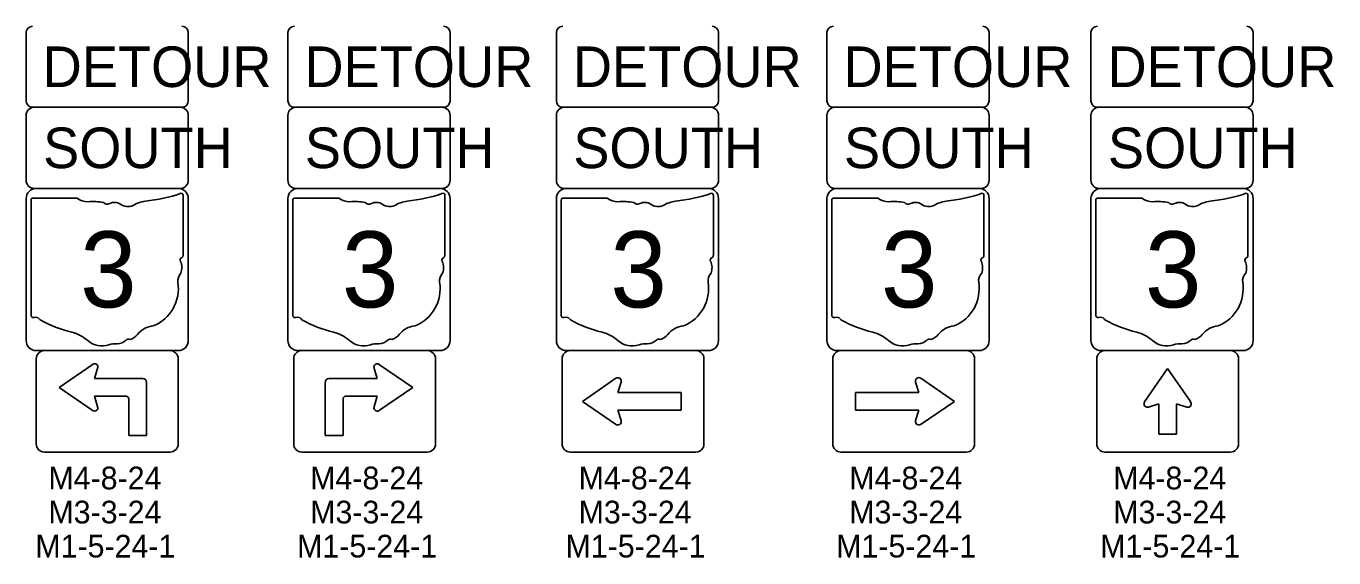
# Model space of a CAD drawing. Extents: x -15.3 to 34, y 0 to 22.
# Drawn here: x -14.79 to -6.73, y 8.37 to 11.65 of the extents above; entities that cross this region are included whole.
import ezdxf

# ---------------------------------------------------------------- set-up
doc = ezdxf.new("R2010")
doc.units = 0
doc.layers.add('SC_Scratch1', color=7, linetype='Continuous')
doc.layers.add('SN_P_Signs', color=7, linetype='Continuous')

msp = doc.modelspace()

# ---------------------------------------------------------------- linework, layer by layer
at = {"layer": 'SN_P_Signs'}
for p, q in [((-14.7405, 11.15), (-13.8405, 11.15)), ((-13.1262, 11.15), (-12.2262, 11.15)), ((-11.4709, 11.15), (-10.5709, 11.15)), ((-9.8019, 11.15), (-8.9019, 11.15)), ((-8.1739, 11.15), (-7.2739, 11.15)), ((-14.7905, 10.7), (-14.7905, 11.1)), ((-13.7905, 11.1), (-13.7905, 10.7)), ((-13.1762, 10.7), (-13.1762, 11.1)), ((-12.1762, 11.1), (-12.1762, 10.7)), ((-11.5209, 10.7), (-11.5209, 11.1)), ((-10.5209, 11.1), (-10.5209, 10.7)), ((-9.8519, 10.7), (-9.8519, 11.1)), ((-8.8519, 11.1), (-8.8519, 10.7)), ((-8.2239, 10.7), (-8.2239, 11.1)), ((-7.2239, 11.1), (-7.2239, 10.7)), ((-13.8405, 10.65), (-14.7405, 10.65)), ((-12.2262, 10.65), (-13.1262, 10.65)), ((-10.5709, 10.65), (-11.4709, 10.65)), ((-8.9019, 10.65), (-9.8019, 10.65)), ((-7.2739, 10.65), (-8.1739, 10.65)), ((-14.7599, 10.578), (-14.7599, 9.8664)), ((-14.4761, 10.5902), (-14.7507, 10.5902)), ((-13.8224, 10.2356), (-13.8224, 10.6078)), ((-13.1456, 10.578), (-13.1456, 9.8664)), ((-12.8619, 10.5902), (-13.1364, 10.5902)), ((-12.2082, 10.2356), (-12.2082, 10.6078)), ((-11.4903, 10.578), (-11.4903, 9.8664)), ((-11.2065, 10.5902), (-11.4811, 10.5902)), ((-10.5528, 10.2356), (-10.5528, 10.6078)), ((-9.8213, 10.578), (-9.8213, 9.8664)), ((-9.5376, 10.5902), (-9.8121, 10.5902)), ((-8.8838, 10.2356), (-8.8838, 10.6078)), ((-8.1934, 10.578), (-8.1934, 9.8664)), ((-7.9096, 10.5902), (-8.1841, 10.5902)), ((-7.2559, 10.2356), (-7.2559, 10.6078)), ((-13.8225, 10.2357), (-13.8224, 10.2356)), ((-12.2083, 10.2357), (-12.2082, 10.2356)), ((-10.5529, 10.2357), (-10.5528, 10.2356)), ((-8.8839, 10.2357), (-8.8838, 10.2356)), ((-7.256, 10.2357), (-7.2559, 10.2356)), ((-14.728, 9.075), (-14.728, 9.6)), ((-14.678, 9.65), (-13.903, 9.65)), ((-13.853, 9.6), (-13.853, 9.075)), ((-13.1408, 9.6), (-13.1408, 9.075)), ((-12.3158, 9.65), (-13.0908, 9.65)), ((-12.2658, 9.075), (-12.2658, 9.6)), ((-11.4855, 9.6), (-11.4855, 9.075)), ((-10.6605, 9.65), (-11.4355, 9.65)), ((-10.6605, 9.65), (-10.6605, 9.65)), ((-10.6105, 9.075), (-10.6105, 9.6)), ((-9.8165, 9.075), (-9.8165, 9.6)), ((-9.7665, 9.65), (-8.9915, 9.65)), ((-8.9415, 9.6), (-8.9415, 9.075)), ((-8.1886, 9.075), (-8.1886, 9.6)), ((-8.1386, 9.65), (-7.3636, 9.65)), ((-7.3136, 9.6), (-7.3136, 9.075)), ((-14.3833, 9.5632), (-14.5873, 9.4234)), ((-14.3685, 9.4781), (-14.3477, 9.5484)), ((-12.6253, 9.4781), (-12.6461, 9.5484)), ((-12.6105, 9.5632), (-12.4065, 9.4234)), ((-7.8932, 9.3337), (-7.7511, 9.5406)), ((-7.7511, 9.5406), (-7.6113, 9.3366)), ((-14.0716, 9.4781), (-14.3685, 9.4781)), ((-14.0716, 9.4781), (-14.0716, 9.4781)), ((-14.0482, 9.1265), (-14.0482, 9.4547)), ((-12.9456, 9.1265), (-12.9456, 9.4547)), ((-12.9222, 9.4781), (-12.6253, 9.4781)), ((-12.9222, 9.4781), (-12.9222, 9.4781)), ((-11.3605, 9.3375), (-11.1536, 9.4797)), ((-11.1219, 9.4564), (-11.1418, 9.3922)), ((-9.3052, 9.4564), (-9.2853, 9.3922)), ((-9.0665, 9.3375), (-9.2735, 9.4797)), ((-14.5873, 9.4234), (-14.3833, 9.2837)), ((-14.3477, 9.2984), (-14.3685, 9.3687)), ((-14.3685, 9.3687), (-14.1732, 9.3687)), ((-12.6253, 9.3687), (-12.8206, 9.3687)), ((-12.6461, 9.2984), (-12.6253, 9.3687)), ((-12.4065, 9.4234), (-12.6105, 9.2837)), ((-11.1418, 9.3922), (-10.7512, 9.3922)), ((-10.7512, 9.3922), (-10.7512, 9.2828)), ((-9.2853, 9.3922), (-9.6759, 9.3922)), ((-9.6759, 9.3922), (-9.6759, 9.2828)), ((-14.1576, 9.3531), (-14.1576, 9.1265)), ((-12.8362, 9.3531), (-12.8362, 9.1265)), ((-11.1565, 9.1978), (-11.3605, 9.3375)), ((-10.7512, 9.2828), (-11.1418, 9.2828)), ((-11.1418, 9.2828), (-11.1219, 9.2187)), ((-9.6759, 9.2828), (-9.2853, 9.2828)), ((-9.2853, 9.2828), (-9.3052, 9.2187)), ((-9.2705, 9.1978), (-9.0665, 9.3375)), ((-7.8058, 9.3219), (-7.8699, 9.3019)), ((-7.8058, 9.1344), (-7.8058, 9.3219)), ((-7.6322, 9.3019), (-7.6964, 9.3219)), ((-7.6964, 9.3219), (-7.6964, 9.1344)), ((-14.1576, 9.1265), (-14.0482, 9.1265)), ((-14.1576, 9.1265), (-14.0482, 9.1265)), ((-12.8362, 9.1265), (-12.9456, 9.1265)), ((-7.6964, 9.1344), (-7.8058, 9.1344)), ((-13.903, 9.025), (-14.678, 9.025)), ((-13.0908, 9.025), (-12.3158, 9.025)), ((-11.4355, 9.025), (-10.6605, 9.025)), ((-8.9915, 9.025), (-9.7665, 9.025)), ((-7.3636, 9.025), (-8.1386, 9.025))]:
    msp.add_line(p, q, dxfattribs=at)
for points in [[(-14.7905, 11.61), (-14.7905, 11.19)], [(-13.7905, 11.19), (-13.7905, 11.61)], [(-13.1762, 11.61), (-13.1762, 11.19)], [(-12.1762, 11.19), (-12.1762, 11.61)], [(-11.5209, 11.61), (-11.5209, 11.19)], [(-10.5209, 11.19), (-10.5209, 11.61)], [(-9.8519, 11.61), (-9.8519, 11.19)], [(-8.8519, 11.19), (-8.8519, 11.61)], [(-8.2239, 11.61), (-8.2239, 11.19)], [(-7.2239, 11.19), (-7.2239, 11.61)], [(-14.7505, 11.15), (-13.8305, 11.15)], [(-13.1362, 11.15), (-12.2162, 11.15)], [(-11.4809, 11.15), (-10.5609, 11.15)], [(-9.8119, 11.15), (-8.8919, 11.15)], [(-8.1839, 11.15), (-7.2639, 11.15)], [(-13.853, 10.65), (-14.728, 10.65)], [(-12.2387, 10.65), (-13.1137, 10.65)], [(-10.5834, 10.65), (-11.4584, 10.65)], [(-8.9144, 10.65), (-9.7894, 10.65)], [(-7.2864, 10.65), (-8.1614, 10.65)], [(-14.7905, 10.5875), (-14.7905, 9.7125)], [(-13.7905, 9.7125), (-13.7905, 10.5875)], [(-13.1762, 10.5875), (-13.1762, 9.7125)], [(-12.1762, 9.7125), (-12.1762, 10.5875)], [(-11.5209, 10.5875), (-11.5209, 9.7125)], [(-10.5209, 9.7125), (-10.5209, 10.5875)], [(-9.8519, 10.5875), (-9.8519, 9.7125)], [(-8.8519, 9.7125), (-8.8519, 10.5875)], [(-8.2239, 10.5875), (-8.2239, 9.7125)], [(-7.2239, 9.7125), (-7.2239, 10.5875)], [(-14.728, 9.65), (-13.853, 9.65)], [(-13.1137, 9.65), (-12.2387, 9.65)], [(-11.4584, 9.65), (-10.5834, 9.65)], [(-9.7894, 9.65), (-8.9144, 9.65)], [(-8.1614, 9.65), (-7.2864, 9.65)]]:
    msp.add_lwpolyline(points, dxfattribs=at)
for centre, radius, start, end in [((-14.7505, 11.61), 0.04, 90, 180), ((-13.8305, 11.61), 0.04, 0, 90), ((-13.1362, 11.61), 0.04, 90, 180), ((-12.2162, 11.61), 0.04, 0, 90), ((-11.4809, 11.61), 0.04, 90, 180), ((-10.5609, 11.61), 0.04, 0, 90), ((-9.8119, 11.61), 0.04, 90, 180), ((-8.8919, 11.61), 0.04, 0, 90), ((-8.1839, 11.61), 0.04, 90, 180), ((-7.2639, 11.61), 0.04, 0, 90), ((-14.7505, 11.19), 0.04, 180, 270), ((-14.7405, 11.1), 0.05, 90, 180), ((-13.8405, 11.1), 0.05, 0, 90), ((-13.8305, 11.19), 0.04, 270, 0), ((-13.1362, 11.19), 0.04, 180, 270), ((-13.1262, 11.1), 0.05, 90, 180), ((-12.2262, 11.1), 0.05, 0, 90), ((-12.2162, 11.19), 0.04, 270, 0), ((-11.4809, 11.19), 0.04, 180, 270), ((-11.4709, 11.1), 0.05, 90, 180), ((-10.5709, 11.1), 0.05, 0, 90), ((-10.5609, 11.19), 0.04, 270, 0), ((-9.8119, 11.19), 0.04, 180, 270), ((-9.8019, 11.1), 0.05, 90, 180), ((-8.9019, 11.1), 0.05, 0, 90), ((-8.8919, 11.19), 0.04, 270, 0), ((-8.1839, 11.19), 0.04, 180, 270), ((-8.1739, 11.1), 0.05, 90, 180), ((-7.2739, 11.1), 0.05, 0, 90), ((-7.2639, 11.19), 0.04, 270, 0), ((-14.7405, 10.7), 0.05, 180, 270), ((-14.728, 10.5875), 0.0625, 90, 180), ((-13.853, 10.5875), 0.0625, 0, 90), ((-13.8405, 10.7), 0.05, 270, 0), ((-13.1262, 10.7), 0.05, 180, 270), ((-13.1137, 10.5875), 0.0625, 90, 180), ((-12.2387, 10.5875), 0.0625, 0, 90), ((-12.2262, 10.7), 0.05, 270, 0), ((-11.4709, 10.7), 0.05, 180, 270), ((-11.4584, 10.5875), 0.0625, 90, 180), ((-10.5834, 10.5875), 0.0625, 0, 90), ((-10.5709, 10.7), 0.05, 270, 0), ((-9.8019, 10.7), 0.05, 180, 270), ((-9.7894, 10.5875), 0.0625, 90, 180), ((-8.9144, 10.5875), 0.0625, 0, 90), ((-8.9019, 10.7), 0.05, 270, 0), ((-8.1739, 10.7), 0.05, 180, 270), ((-8.1614, 10.5875), 0.0625, 90, 180), ((-7.2864, 10.5875), 0.0625, 0, 90), ((-7.2739, 10.7), 0.05, 270, 0), ((-14.7492, 10.5795), 0.0109, 98.1301, 188.1301), ((-14.4108, 10.6728), 0.1053, 231.61951, 271.11188), ((-14.3758, 10.1907), 0.3782, 80.48669, 94.98827), ((-14.2454, 10.5009), 0.0632, 54.46668, 119.14113), ((-14.0296, 10.3729), 0.2, 97.34618, 120.76885), ((-14.1564, 11.5603), 0.9942, 275.84447, 288.90645), ((-13.8328, 10.6094), 0.0104, 351.86209, 97.738), ((-13.1349, 10.5795), 0.0109, 98.1301, 188.1301), ((-12.7965, 10.6728), 0.1053, 231.61951, 271.11188), ((-12.7616, 10.1907), 0.3782, 80.48669, 94.98827), ((-12.6311, 10.5009), 0.0632, 54.46668, 119.14113), ((-12.4153, 10.3729), 0.2, 97.34618, 120.76885), ((-12.5421, 11.5603), 0.9942, 275.84447, 288.90645), ((-12.2186, 10.6094), 0.0104, 351.86209, 97.738), ((-11.4796, 10.5795), 0.0109, 98.1301, 188.1301), ((-11.1412, 10.6728), 0.1053, 231.61951, 271.11188), ((-11.1062, 10.1907), 0.3782, 80.48669, 94.98827), ((-10.9758, 10.5009), 0.0632, 54.46668, 119.14113), ((-10.76, 10.3729), 0.2, 97.34618, 120.76885), ((-10.8868, 11.5603), 0.9942, 275.84447, 288.90645), ((-10.5632, 10.6094), 0.0104, 351.86209, 97.738), ((-9.8106, 10.5795), 0.0109, 98.1301, 188.1301), ((-9.4722, 10.6728), 0.1053, 231.61951, 271.11188), ((-9.4372, 10.1907), 0.3782, 80.48669, 94.98827), ((-9.3068, 10.5009), 0.0632, 54.46668, 119.14113), ((-9.091, 10.3729), 0.2, 97.34618, 120.76885), ((-9.2178, 11.5603), 0.9942, 275.84447, 288.90645), ((-8.8942, 10.6094), 0.0104, 351.86209, 97.738), ((-8.1826, 10.5795), 0.0109, 98.1301, 188.1301), ((-7.8442, 10.6728), 0.1053, 231.61951, 271.11188), ((-7.8093, 10.1907), 0.3782, 80.48669, 94.98827), ((-7.6788, 10.5009), 0.0632, 54.46668, 119.14113), ((-7.463, 10.3729), 0.2, 97.34618, 120.76885), ((-7.5898, 11.5603), 0.9942, 275.84447, 288.90645), ((-7.2663, 10.6094), 0.0104, 351.86209, 97.738), ((-14.29, 10.5832), 0.0304, 219.79206, 297.10237), ((-14.1638, 10.6137), 0.076, 233.85621, 294.82819), ((-12.6757, 10.5832), 0.0304, 219.79206, 297.10237), ((-12.5495, 10.6137), 0.076, 233.85621, 294.82819), ((-11.0204, 10.5832), 0.0304, 219.79206, 297.10237), ((-10.8942, 10.6137), 0.076, 233.85621, 294.82819), ((-9.3514, 10.5832), 0.0304, 219.79206, 297.10237), ((-9.2252, 10.6137), 0.076, 233.85621, 294.82819), ((-7.7234, 10.5832), 0.0304, 219.79206, 297.10237), ((-7.5973, 10.6137), 0.076, 233.85621, 294.82819), ((-13.8248, 10.2083), 0.0162, 107.94398, 210.33697), ((-13.9276, 10.1612), 0.097, 340.03296, 23.64957), ((-13.8336, 10.2342), 0.0112, 289.60381, 7.73413), ((-12.2106, 10.2083), 0.0162, 107.94398, 210.33697), ((-12.3133, 10.1612), 0.097, 340.03296, 23.64957), ((-12.2193, 10.2342), 0.0112, 289.60381, 7.73413), ((-10.5553, 10.2083), 0.0162, 107.94398, 210.33697), ((-10.658, 10.1612), 0.097, 340.03296, 23.64957), ((-10.564, 10.2342), 0.0112, 289.60381, 7.73413), ((-8.8863, 10.2083), 0.0162, 107.94398, 210.33697), ((-8.989, 10.1612), 0.097, 340.03296, 23.64957), ((-8.895, 10.2342), 0.0112, 289.60381, 7.73413), ((-7.2583, 10.2083), 0.0162, 107.94398, 210.33697), ((-7.3611, 10.1612), 0.097, 340.03296, 23.64957), ((-7.267, 10.2342), 0.0112, 289.60381, 7.73413), ((-13.785, 10.0799), 0.0705, 136.8065, 186.92959), ((-12.1708, 10.0799), 0.0705, 136.8065, 186.92959), ((-10.5155, 10.0799), 0.0705, 136.8065, 186.92959), ((-8.8465, 10.0799), 0.0705, 136.8065, 186.92959), ((-7.2185, 10.0799), 0.0705, 136.8065, 186.92959), ((-14.1007, 10.0325), 0.2487, 292.30889, 8.98584), ((-12.4864, 10.0325), 0.2487, 292.30889, 8.98584), ((-10.8311, 10.0325), 0.2487, 292.30889, 8.98584), ((-9.1621, 10.0325), 0.2487, 292.30889, 8.98584), ((-7.5341, 10.0325), 0.2487, 292.30889, 8.98584), ((-14.7491, 9.8649), 0.011, 171.95839, 258.30661), ((-14.7474, 9.9377), 0.0836, 267.33899, 280.60386), ((-14.7303, 9.8254), 0.0302, 29.74838, 93.27175), ((-14.3497, 10.4647), 0.7179, 240.41292, 257.1985), ((-13.1348, 9.8649), 0.011, 171.95839, 258.30661), ((-13.1331, 9.9377), 0.0836, 267.33899, 280.60386), ((-13.116, 9.8254), 0.0302, 29.74838, 93.27175), ((-12.7354, 10.4647), 0.7179, 240.41292, 257.1985), ((-11.4795, 9.8649), 0.011, 171.95839, 258.30661), ((-11.4778, 9.9377), 0.0836, 267.33899, 280.60386), ((-11.4607, 9.8254), 0.0302, 29.74838, 93.27175), ((-11.0801, 10.4647), 0.7179, 240.41292, 257.1985), ((-9.8105, 9.8649), 0.011, 171.95839, 258.30661), ((-9.8088, 9.9377), 0.0836, 267.33899, 280.60386), ((-9.7917, 9.8254), 0.0302, 29.74838, 93.27175), ((-9.4111, 10.4647), 0.7179, 240.41292, 257.1985), ((-8.1825, 9.8649), 0.011, 171.95839, 258.30661), ((-8.1809, 9.9377), 0.0836, 267.33899, 280.60386), ((-8.1638, 9.8254), 0.0302, 29.74838, 93.27175), ((-7.7831, 10.4647), 0.7179, 240.41292, 257.1985), ((-14.5637, 9.5468), 0.2246, 47.18416, 75.83597), ((-13.9958, 9.6667), 0.1362, 94.40312, 142.57675), ((-12.9494, 9.5468), 0.2246, 47.18416, 75.83597), ((-12.3816, 9.6667), 0.1362, 94.40312, 142.57675), ((-11.2941, 9.5468), 0.2246, 47.18416, 75.83597), ((-10.7262, 9.6667), 0.1362, 94.40312, 142.57675), ((-9.6251, 9.5468), 0.2246, 47.18416, 75.83597), ((-9.0572, 9.6667), 0.1362, 94.40312, 142.57675), ((-7.9972, 9.5468), 0.2246, 47.18416, 75.83597), ((-7.4293, 9.6667), 0.1362, 94.40312, 142.57675), ((-14.728, 9.7125), 0.0625, 180, 270), ((-14.3207, 9.8218), 0.1425, 230.70037, 286.29184), ((-14.2384, 9.5758), 0.1171, 85.69512, 111.20995), ((-14.228, 9.7686), 0.0759, 268.77702, 315.54927), ((-14.1593, 9.6996), 0.0214, 65.75173, 132.64842), ((-14.1684, 9.7975), 0.0803, 282.87319, 323.27711), ((-13.853, 9.7125), 0.0625, 270, 0), ((-13.1137, 9.7125), 0.0625, 180, 270), ((-12.7065, 9.8218), 0.1425, 230.70037, 286.29184), ((-12.6241, 9.5758), 0.1171, 85.69512, 111.20995), ((-12.6137, 9.7686), 0.0759, 268.77702, 315.54927), ((-12.545, 9.6996), 0.0214, 65.75173, 132.64842), ((-12.5541, 9.7975), 0.0803, 282.87319, 323.27711), ((-12.2387, 9.7125), 0.0625, 270, 0), ((-11.4584, 9.7125), 0.0625, 180, 270), ((-11.0512, 9.8218), 0.1425, 230.70037, 286.29184), ((-10.9688, 9.5758), 0.1171, 85.69512, 111.20995), ((-10.9584, 9.7686), 0.0759, 268.77702, 315.54927), ((-10.8897, 9.6996), 0.0214, 65.75173, 132.64842), ((-10.8988, 9.7975), 0.0803, 282.87319, 323.27711), ((-10.5834, 9.7125), 0.0625, 270, 0), ((-9.7894, 9.7125), 0.0625, 180, 270), ((-9.3822, 9.8218), 0.1425, 230.70037, 286.29184), ((-9.2998, 9.5758), 0.1171, 85.69512, 111.20995), ((-9.2894, 9.7686), 0.0759, 268.77702, 315.54927), ((-9.2207, 9.6996), 0.0214, 65.75173, 132.64842), ((-9.2298, 9.7975), 0.0803, 282.87319, 323.27711), ((-8.9144, 9.7125), 0.0625, 270, 0), ((-8.1614, 9.7125), 0.0625, 180, 270), ((-7.7542, 9.8218), 0.1425, 230.70037, 286.29184), ((-7.6718, 9.5758), 0.1171, 85.69512, 111.20995), ((-7.6614, 9.7686), 0.0759, 268.77702, 315.54927), ((-7.5927, 9.6996), 0.0214, 65.75173, 132.64842), ((-7.6018, 9.7975), 0.0803, 282.87319, 323.27711), ((-7.2864, 9.7125), 0.0625, 270, 0), ((-14.678, 9.6), 0.05, 90, 180), ((-13.903, 9.6), 0.05, 0, 90), ((-13.0908, 9.6), 0.05, 90, 180), ((-12.3158, 9.6), 0.05, 0, 90), ((-11.4355, 9.6), 0.05, 90, 180), ((-10.6605, 9.6), 0.05, 0, 90), ((-9.7665, 9.6001), 0.05, 90, 180), ((-8.9915, 9.6001), 0.05, 0, 90), ((-8.1386, 9.6001), 0.05, 90, 180), ((-7.3636, 9.6001), 0.05, 0, 90), ((-14.3685, 9.5485), 0.0209, 0.00165, 134.99986), ((-12.6252, 9.5484), 0.0209, 45.00014, 179.99835), ((-14.0717, 9.4547), 0.0234, 0, 90), ((-12.9221, 9.4547), 0.0234, 90, 180), ((-11.1417, 9.4625), 0.0209, 342.79539, 124.58878), ((-9.2853, 9.4626), 0.0209, 55.41122, 197.20461), ((-14.1732, 9.3531), 0.0156, 0, 90), ((-12.8206, 9.3531), 0.0156, 90, 180), ((-14.3685, 9.2985), 0.0209, 225.00014, 0.00165), ((-12.6252, 9.2984), 0.0209, 179.99835, 314.99986), ((-7.8761, 9.3219), 0.0209, 145.41122, 287.20461), ((-7.6261, 9.3219), 0.0209, 252.79539, 45.00956), ((-11.1417, 9.2125), 0.0209, 224.99044, 17.20461), ((-9.2853, 9.2126), 0.0209, 162.79539, 315.00956), ((-14.678, 9.075), 0.05, 180, 270), ((-13.903, 9.075), 0.05, 270, 360), ((-13.0908, 9.075), 0.05, 180, 270), ((-12.3158, 9.075), 0.05, 270, 0), ((-11.4355, 9.075), 0.05, 180, 270), ((-10.6605, 9.075), 0.05, 270, 0), ((-9.7665, 9.0751), 0.05, 180, 270), ((-8.9915, 9.0751), 0.05, 270, 360), ((-8.1386, 9.0751), 0.05, 180, 270), ((-7.3636, 9.0751), 0.05, 270, 0)]:
    msp.add_arc(centre, radius, start, end, dxfattribs=at)

# ---------------------------------------------------------------- texts
at = {"layer": 'SC_Scratch1'}
for s, p in [('M4-8-24', (-14.6533, 8.7949)), ('M4-8-24', (-13.039, 8.7949)), ('M4-8-24', (-11.3837, 8.7949)), ('M4-8-24', (-9.7147, 8.7949)), ('M4-8-24', (-8.0868, 8.7949)), ('M3-3-24', (-14.6533, 8.5849)), ('M3-3-24', (-13.039, 8.5849)), ('M3-3-24', (-11.3837, 8.5849)), ('M3-3-24', (-9.7147, 8.5849)), ('M3-3-24', (-8.0868, 8.5849)), ('M1-5-24-1', (-14.7339, 8.3749)), ('M1-5-24-1', (-13.1196, 8.3749)), ('M1-5-24-1', (-11.4643, 8.3749)), ('M1-5-24-1', (-9.7953, 8.3749)), ('M1-5-24-1', (-8.1673, 8.3749))]:
    msp.add_text(s, height=0.14, dxfattribs=at).set_placement(p)
at = {"layer": 'SN_P_Signs'}
for s, height, p in [('DETOUR', 0.25, (-14.6888, 11.275)), ('DETOUR', 0.25, (-13.0746, 11.275)), ('DETOUR', 0.25, (-11.4193, 11.275)), ('DETOUR', 0.25, (-9.7503, 11.275)), ('DETOUR', 0.25, (-8.1223, 11.275)), ('SOUTH', 0.25, (-14.6861, 10.775)), ('SOUTH', 0.25, (-13.0719, 10.775)), ('SOUTH', 0.25, (-11.4165, 10.775)), ('SOUTH', 0.25, (-9.7475, 10.775)), ('SOUTH', 0.25, (-8.1196, 10.775)), ('3', 0.4688, (-14.4577, 9.9166)), ('3', 0.4688, (-12.8434, 9.9166)), ('3', 0.4688, (-11.1881, 9.9166)), ('3', 0.4688, (-9.5191, 9.9166)), ('3', 0.4688, (-7.8911, 9.9166))]:
    msp.add_text(s, height=height, dxfattribs=at).set_placement(p)

doc.saveas('drawing.dxf')
